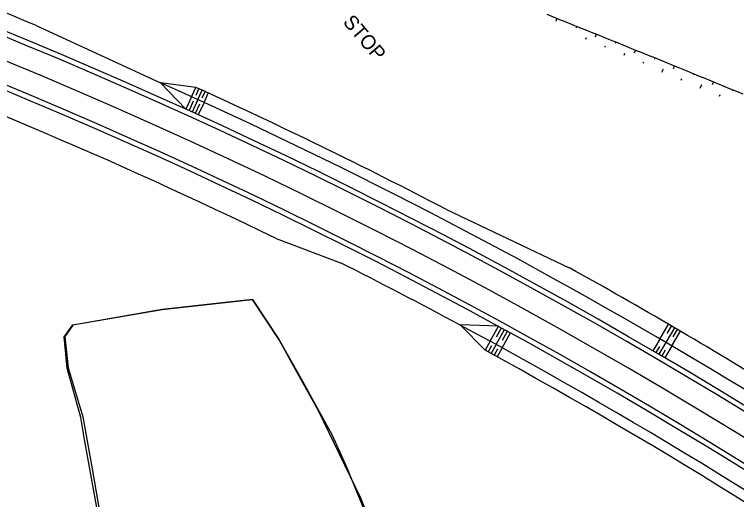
# Model space of a CAD drawing. Extents: x -552278 to -547230, y -1151007 to -1148251.
# Drawn here: x -550769.8 to -550664.2, y -1148912.8 to -1148841.8 of the extents above; entities that cross this region are included whole.
import ezdxf

# ---------------------------------------------------------------- set-up
doc = ezdxf.new("R2010")
doc.units = 0
for name, color, linetype in [('u_hranice BC3', 7, 'Continuous'), ('u_SDZ', 7, 'Continuous'), ('u_STAVENIŠTĚ', 7, 'Continuous'), ('u_stávající stromy', 7, 'Continuous'), ('u_trat navrh', 7, 'Continuous')]:
    doc.layers.add(name, color=color, linetype=linetype)

msp = doc.modelspace()

# ---------------------------------------------------------------- linework, layer by layer
at = {"layer": 'u_hranice BC3'}
msp.add_lwpolyline([(-550714.71, -1148923.94), (-550719.15, -1148912.6), (-550725.33, -1148899.8), (-550729.18, -1148892.89), (-550731.1, -1148889.43), (-550735.02, -1148883.54), (-550736.8, -1148883.74), (-550748.22, -1148884.98), (-550761.27, -1148887.31), (-550762.44, -1148888.96), (-550761.97, -1148893.55), (-550759.82, -1148900.67), (-550758.47, -1148908.3), (-550757.13, -1148915.93)], dxfattribs=at)
at = {"layer": 'u_STAVENIŠTĚ'}
msp.add_lwpolyline([(-550756.92, -1148918.54), (-550759.58, -1148904), (-550760.11, -1148900.8), (-550762.11, -1148893.59), (-550762.56, -1148888.97), (-550761.3, -1148887.22), (-550748.22, -1148884.98), (-550736.8, -1148883.74), (-550735.02, -1148883.54), (-550731.1, -1148889.43), (-550727.69, -1148895.5), (-550723.41, -1148903.26), (-550721.28, -1148907.93), (-550714.71, -1148923.93)], dxfattribs=at)
at = {"layer": 'u_stávající stromy'}
msp.add_lwpolyline([(-550714.71, -1148923.94), (-550719.15, -1148912.6), (-550725.33, -1148899.8), (-550729.18, -1148892.89), (-550731.1, -1148889.43), (-550735.02, -1148883.54), (-550736.8, -1148883.74), (-550748.22, -1148884.98), (-550761.27, -1148887.31), (-550762.44, -1148888.96), (-550761.97, -1148893.55), (-550759.82, -1148900.67), (-550758.47, -1148908.3), (-550757.13, -1148915.93)], dxfattribs=at)
at = {"layer": 'u_trat navrh'}
for p, q in [((-550690.46, -1148842.43), (-550690.64, -1148842.88)), ((-550766.65, -1148843.45), (-550748.47, -1148851.82)), ((-550687.59, -1148843.57), (-550687.67, -1148843.78)), ((-550684.72, -1148844.72), (-550684.9, -1148845.18)), ((-550686.24, -1148845.45), (-550686.16, -1148845.23)), ((-550681.86, -1148845.88), (-550681.94, -1148846.08)), ((-550683.44, -1148846.61), (-550683.39, -1148846.5)), ((-550679, -1148847.04), (-550679.18, -1148847.49)), ((-550680.64, -1148847.78), (-550680.52, -1148847.5)), ((-550676.14, -1148848.2), (-550676.22, -1148848.4)), ((-550677.85, -1148848.98), (-550677.78, -1148848.83)), ((-550673.28, -1148849.36), (-550673.46, -1148849.81)), ((-550675.12, -1148850.3), (-550674.89, -1148849.79)), ((-550672.32, -1148851.47), (-550672.22, -1148851.23)), ((-550670.42, -1148850.53), (-550670.5, -1148850.73)), ((-550743.29, -1148852.51), (-550748.47, -1148851.82)), ((-550744.74, -1148855.69), (-550748.47, -1148851.82)), ((-550743.91, -1148853.87), (-550743.29, -1148852.51)), ((-550669.52, -1148852.64), (-550669.29, -1148852.08)), ((-550667.56, -1148851.7), (-550667.75, -1148852.15)), ((-550743.25, -1148853.63), (-550742.83, -1148852.72)), ((-550743, -1148854.29), (-550742.38, -1148852.92)), ((-550742.34, -1148854.04), (-550741.92, -1148853.13)), ((-550742.09, -1148854.7), (-550741.47, -1148853.34)), ((-550666.71, -1148853.79), (-550666.6, -1148853.54)), ((-550664.71, -1148852.87), (-550664.79, -1148853.08)), ((-550743.91, -1148853.87), (-550744.74, -1148855.69)), ((-550743.66, -1148854.54), (-550744.28, -1148855.9)), ((-550743, -1148854.29), (-550743.83, -1148856.11)), ((-550742.09, -1148854.7), (-550742.92, -1148856.52)), ((-550742.75, -1148854.95), (-550743.37, -1148856.31)), ((-550706.73, -1148870.31), (-550688.66, -1148878.9)), ((-550731.54, -1148874.61), (-550722.14, -1148878.15)), ((-550699.04, -1148887.45), (-550704.63, -1148887.26)), ((-550700.96, -1148890.96), (-550704.63, -1148887.26)), ((-550700.24, -1148889.64), (-550699.04, -1148887.45)), ((-550675.41, -1148889.31), (-550674.15, -1148887.15)), ((-550674.34, -1148888.49), (-550673.71, -1148887.41)), ((-550699.36, -1148890.12), (-550698.16, -1148887.93)), ((-550699.32, -1148889.01), (-550698.6, -1148887.69)), ((-550698.48, -1148890.61), (-550697.28, -1148888.41)), ((-550698.44, -1148889.49), (-550697.72, -1148888.17)), ((-550673.28, -1148887.66), (-550674.54, -1148889.82)), ((-550673.68, -1148890.33), (-550672.42, -1148888.17)), ((-550673.48, -1148888.99), (-550672.85, -1148887.91)), ((-550675.41, -1148889.31), (-550676.42, -1148891.04)), ((-550700.24, -1148889.64), (-550700.96, -1148890.96)), ((-550700.04, -1148890.32), (-550700.52, -1148891.2)), ((-550699.36, -1148890.12), (-550700.08, -1148891.44)), ((-550698.48, -1148890.61), (-550699.2, -1148891.92)), ((-550675.48, -1148890.43), (-550675.98, -1148891.29)), ((-550674.54, -1148889.82), (-550675.55, -1148891.54)), ((-550673.68, -1148890.32), (-550674.69, -1148892.05)), ((-550699.16, -1148890.8), (-550699.64, -1148891.68)), ((-550674.62, -1148890.93), (-550675.12, -1148891.8))]:
    msp.add_line(p, q, dxfattribs=at)
msp.add_lwpolyline([(-550691.97, -1148841.82), (-550691.04, -1148842.19), (-550690.11, -1148842.56), (-550689.18, -1148842.94), (-550688.26, -1148843.31), (-550687.33, -1148843.68), (-550686.4, -1148844.05), (-550685.48, -1148844.42), (-550684.55, -1148844.79), (-550683.62, -1148845.17), (-550682.7, -1148845.54), (-550681.77, -1148845.91), (-550680.84, -1148846.29), (-550679.92, -1148846.66), (-550678.99, -1148847.04), (-550678.07, -1148847.41), (-550677.14, -1148847.79), (-550676.22, -1148848.16), (-550675.29, -1148848.54), (-550674.37, -1148848.92), (-550673.44, -1148849.29), (-550672.52, -1148849.67), (-550671.59, -1148850.05), (-550670.67, -1148850.43), (-550669.74, -1148850.8), (-550668.82, -1148851.18), (-550667.9, -1148851.56), (-550666.97, -1148851.94), (-550666.05, -1148852.32), (-550665.12, -1148852.7), (-550664.2, -1148853.08), (-550663.28, -1148853.46)], dxfattribs=at)
for radius, start, end in [(756.5, 67.46341, 76.89047), (754, 51.79075, 76.89047), (753.25, 51.79075, 76.89047), (750, 47.42068, 76.89047), (746.75, 47.42068, 72.23343), (746, 47.42068, 72.23343), (742.5, 64.03774, 70.13589), (756, 51.79075, 65.9476), (757.5, 62.49278, 65.56866), (743.5, 61.74591, 63.26712), (758.5, 58.30817, 60.98197), (743.5, 47.42068, 61.74591), (742, 47.42068, 61.3606)]:
    msp.add_arc((-551056.59, -1149542.18), radius, start, end, dxfattribs=at)

# ---------------------------------------------------------------- texts
at = {"layer": 'u_SDZ'}
msp.add_text('STOP', height=2.1, rotation=310.5142, dxfattribs=at).set_placement((-550721.88, -1148843.01))

doc.saveas('drawing.dxf')
